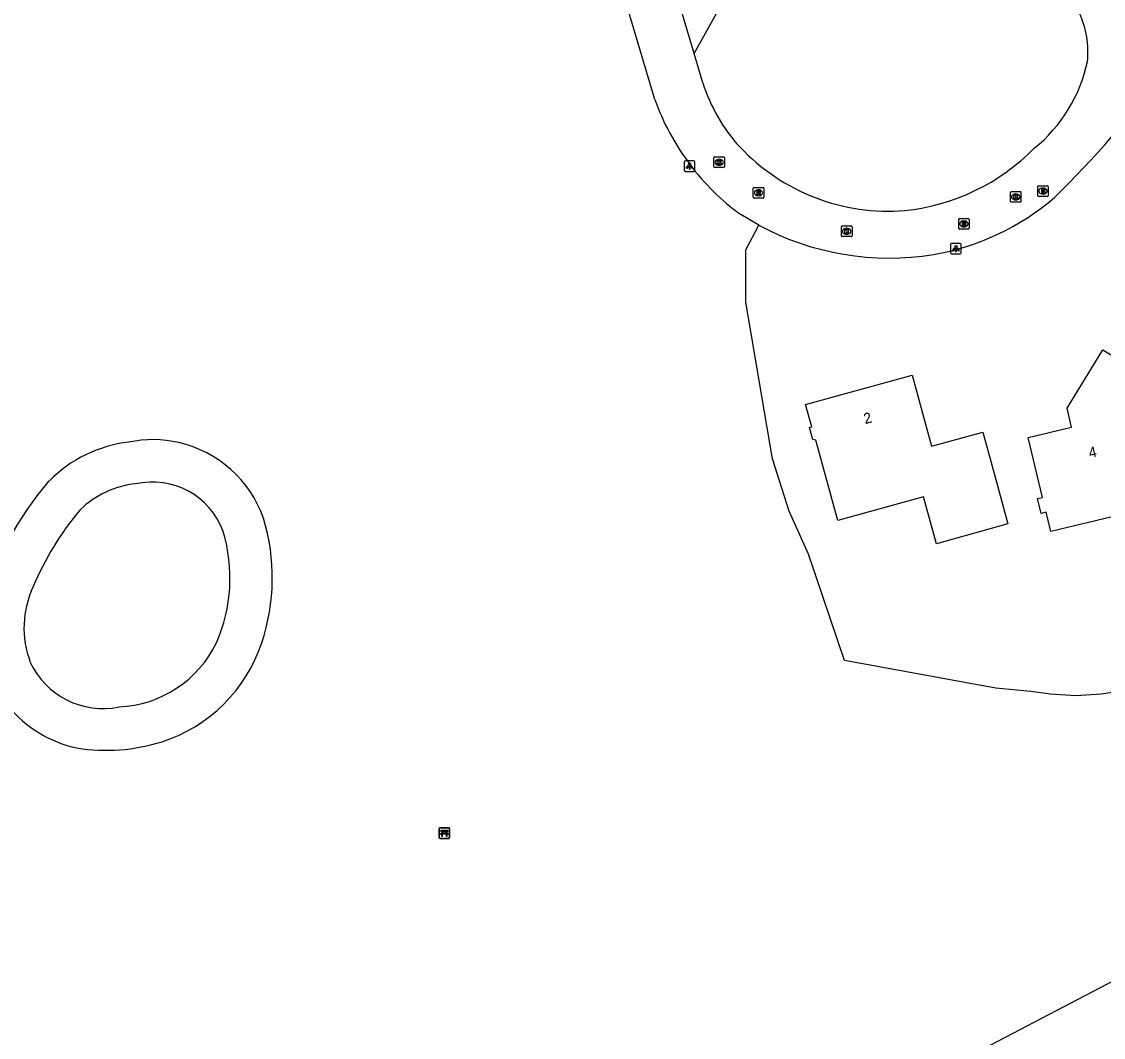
# Model space of a CAD drawing. Extents: x 162157 to 163165, y 378998 to 380775.
# Drawn here: x 162596.4 to 162698.9, y 380061.7 to 380157.8 of the extents above; entities that cross this region are included whole.
import ezdxf

# ---------------------------------------------------------------- set-up
doc = ezdxf.new("R2010")
doc.units = 0
for name, color, linetype in [('IMGEO_Bank', 7, 'Continuous'), ('IMGEO_Brandkraan', 7, 'Continuous'), ('IMGEO_Kolk', 7, 'Continuous'), ('IMGEO_Lichtpunt', 7, 'Continuous'), ('IMGEO_Meer_plas_ven_vijver', 7, 'Continuous'), ('IMGEO_Naaldbos', 7, 'Continuous'), ('IMGEO_Pand', 7, 'Continuous'), ('IMGEO_Pand_nummerreeks', 7, 'Continuous'), ('IMGEO_Rijbaan_lokaal_open', 7, 'Continuous'), ('IMGEO_Rioolput', 7, 'Continuous')]:
    doc.layers.add(name, color=color, linetype=linetype)

msp = doc.modelspace()

# ---------------------------------------------------------------- linework, layer by layer
at = {"layer": 'IMGEO_Bank'}
for p, q in [((162635.96, 380080.55), (162635.96, 380081.39)), ((162635.96, 380081.39), (162635.96, 380080.55)), ((162636.03, 380081.48), (162636.87, 380081.48)), ((162636.87, 380081.48), (162636.03, 380081.48)), ((162636.65, 380080.88), (162636.26, 380080.88)), ((162636.27, 380080.99), (162636.27, 380081.09)), ((162636.31, 380081.09), (162636.31, 380080.99)), ((162636.6, 380081.1), (162636.32, 380081.1)), ((162636.32, 380080.98), (162636.6, 380080.98)), ((162636.6, 380080.99), (162636.6, 380081.09)), ((162636.65, 380081.09), (162636.65, 380080.99)), ((162636.96, 380081.4), (162636.96, 380080.56)), ((162636.96, 380080.56), (162636.96, 380081.4)), ((162636.88, 380080.48), (162636.04, 380080.48)), ((162636.04, 380080.48), (162636.88, 380080.48))]:
    msp.add_line(p, q, dxfattribs=at)
for points in [[(162636.2, 380080.88), (162636.06, 380080.88), (162636.17, 380080.98), (162636.26, 380080.98)], [(162636.26, 380081.1), (162636.17, 380081.1), (162636.17, 380081.26), (162636.74, 380081.26), (162636.74, 380081.1), (162636.65, 380081.1)], [(162636.25, 380080.87), (162636.25, 380080.66), (162636.21, 380080.66), (162636.21, 380080.87)], [(162636.65, 380080.98), (162636.74, 380080.98), (162636.85, 380080.88), (162636.71, 380080.88)], [(162636.7, 380080.87), (162636.7, 380080.66), (162636.66, 380080.66), (162636.66, 380080.87)]]:
    msp.add_lwpolyline(points, dxfattribs=at)
for centre, radius, start, end in [((162636.04, 380081.4), 0.0779, 92.4484, 184.2845), ((162636.04, 380081.4), 0.0779, 92.4484, 184.2845), ((162636.2, 380080.87), 0.00671, 2.8957, 87.1043), ((162636.26, 380080.87), 0.00671, 92.8957, 177.1043), ((162636.26, 380081.09), 0.00671, 2.8957, 87.1043), ((162636.26, 380080.99), 0.00671, 272.8957, 357.1043), ((162636.32, 380081.09), 0.00671, 92.8957, 177.1043), ((162636.32, 380080.99), 0.00671, 182.8957, 267.1043), ((162636.6, 380081.09), 0.00671, 2.8957, 87.1043), ((162636.6, 380080.99), 0.00671, 272.8957, 357.1043), ((162636.65, 380081.09), 0.00671, 92.8957, 177.1043), ((162636.65, 380080.99), 0.00671, 182.8957, 267.1043), ((162636.65, 380080.87), 0.00671, 2.8957, 87.1043), ((162636.71, 380080.87), 0.00671, 92.8957, 177.1043), ((162636.88, 380081.4), 0.0779, 2.4484, 94.2845), ((162636.88, 380081.4), 0.0779, 2.4484, 94.2845), ((162636.04, 380080.56), 0.0779, 182.4484, 274.2845), ((162636.04, 380080.56), 0.0779, 182.4484, 274.2845), ((162636.88, 380080.56), 0.0779, 272.4484, 4.2845), ((162636.88, 380080.56), 0.0779, 272.4484, 4.2845)]:
    msp.add_arc(centre, radius, start, end, dxfattribs=at)
at = {"layer": 'IMGEO_Brandkraan'}
for p, q in [((162692.64, 380141.31), (162692.64, 380142.17)), ((162692.72, 380142.24), (162693.57, 380142.24)), ((162693.64, 380142.17), (162693.64, 380141.31)), ((162693.57, 380141.24), (162692.72, 380141.24)), ((162693.13, 380142.02), (162693.15, 380142.02)), ((162693.15, 380141.46), (162693.13, 380141.46))]:
    msp.add_line(p, q, dxfattribs=at)
for points in [[(162692.64, 380141.31), (162692.64, 380142.17)], [(162692.72, 380142.24), (162693.57, 380142.24)], [(162693.64, 380142.17), (162693.64, 380141.31)], [(162693.57, 380141.24), (162692.72, 380141.24)], [(162692.99, 380141.94), (162692.99, 380141.54), (162693.2, 380141.54)], [(162693.22, 380141.94), (162692.99, 380141.94)], [(162693.17, 380141.86), (162693.11, 380141.86), (162693.11, 380141.78)], [(162693.11, 380141.78), (162693.17, 380141.78)], [(162693.18, 380141.71), (162693.11, 380141.71), (162693.11, 380141.62)], [(162693.11, 380141.62), (162693.18, 380141.62)]]:
    msp.add_lwpolyline(points, dxfattribs=at)
for centre, radius, start, end in [((162692.72, 380142.16), 0.0765, 91.552, 178.448), ((162692.72, 380142.16), 0.0765, 91.552, 178.448), ((162693.57, 380142.16), 0.0765, 1.552, 88.448), ((162693.57, 380142.16), 0.0765, 1.552, 88.448), ((162692.72, 380141.31), 0.0765, 181.552, 268.448), ((162692.72, 380141.31), 0.0765, 181.552, 268.448), ((162693.17, 380141.82), 0.0379, 267.8285, 90.9355), ((162693.18, 380141.67), 0.0404, 269.8759, 90.5077), ((162693.21, 380141.79), 0.251, 268.6676, 293.5347), ((162693.22, 380141.79), 0.145, 59.4692, 91.5367), ((162693.25, 380141.84), 0.0922, 285.5137, 58.1501), ((162693.25, 380141.65), 0.105, 301.3115, 78.989), ((162693.57, 380141.31), 0.0765, 271.552, 358.448), ((162693.57, 380141.31), 0.0765, 271.552, 358.448)]:
    msp.add_arc(centre, radius, start, end, dxfattribs=at)
for centre, major_axis, ratio, start_param, end_param in [((162693.13, 380141.74), (-0.387, 0.002), 0.722429, 4.712389, 7.853982), ((162693.15, 380141.74), (-0.39, 0.002), 0.717154, 1.570796, 4.712389)]:
    msp.add_ellipse(centre, major_axis=major_axis, ratio=ratio, start_param=start_param, end_param=end_param, dxfattribs=at)
at = {"layer": 'IMGEO_Kolk'}
for p, q in [((162661.98, 380144.05), (162661.98, 380144.9)), ((162662.05, 380144.97), (162662.91, 380144.97)), ((162662.47, 380144.75), (162662.49, 380144.75)), ((162662.49, 380144.19), (162662.47, 380144.19)), ((162662.98, 380144.9), (162662.98, 380144.05)), ((162662.91, 380143.97), (162662.05, 380143.97)), ((162690.06, 380140.77), (162690.06, 380141.62)), ((162690.14, 380141.69), (162690.99, 380141.69)), ((162690.55, 380141.47), (162690.58, 380141.47)), ((162691.06, 380141.62), (162691.06, 380140.77)), ((162690.99, 380140.69), (162690.14, 380140.69)), ((162690.57, 380140.91), (162690.55, 380140.91)), ((162674.06, 380137.51), (162674.06, 380138.36)), ((162674.13, 380138.44), (162674.98, 380138.44)), ((162674.54, 380138.22), (162674.57, 380138.22)), ((162675.06, 380138.36), (162675.06, 380137.51)), ((162674.98, 380137.44), (162674.13, 380137.44)), ((162674.57, 380137.66), (162674.54, 380137.66))]:
    msp.add_line(p, q, dxfattribs=at)
for points in [[(162661.98, 380144.05), (162661.98, 380144.9)], [(162662.05, 380144.97), (162662.91, 380144.97)], [(162662.3, 380144.67), (162662.42, 380144.67), (162662.42, 380144.52), (162662.55, 380144.67), (162662.72, 380144.67), (162662.57, 380144.52), (162662.72, 380144.27), (162662.57, 380144.27), (162662.49, 380144.44), (162662.42, 380144.37), (162662.42, 380144.27), (162662.3, 380144.27), (162662.3, 380144.67)], [(162662.98, 380144.9), (162662.98, 380144.05)], [(162662.91, 380143.97), (162662.05, 380143.97)], [(162690.06, 380140.77), (162690.06, 380141.62)], [(162690.14, 380141.69), (162690.99, 380141.69)], [(162690.38, 380141.39), (162690.51, 380141.39), (162690.51, 380141.24), (162690.64, 380141.39), (162690.8, 380141.39), (162690.66, 380141.24), (162690.81, 380140.99), (162690.66, 380140.99), (162690.57, 380141.16), (162690.51, 380141.09), (162690.51, 380140.99), (162690.38, 380140.99), (162690.38, 380141.39)], [(162691.06, 380141.62), (162691.06, 380140.77)], [(162690.99, 380140.69), (162690.14, 380140.69)], [(162674.06, 380137.51), (162674.06, 380138.36)], [(162674.13, 380138.44), (162674.98, 380138.44)], [(162674.38, 380138.14), (162674.5, 380138.14), (162674.5, 380137.98), (162674.63, 380138.14), (162674.79, 380138.14), (162674.65, 380137.99), (162674.8, 380137.74), (162674.65, 380137.74), (162674.56, 380137.9), (162674.5, 380137.83), (162674.5, 380137.74), (162674.38, 380137.74), (162674.38, 380138.14)], [(162675.06, 380138.36), (162675.06, 380137.51)], [(162674.98, 380137.44), (162674.13, 380137.44)]]:
    msp.add_lwpolyline(points, dxfattribs=at)
for centre, start, end in [((162662.06, 380144.9), 91.552, 178.448), ((162662.06, 380144.9), 91.552, 178.448), ((162662.9, 380144.9), 1.552, 88.448), ((162662.9, 380144.9), 1.552, 88.448), ((162662.06, 380144.05), 181.552, 268.448), ((162662.06, 380144.05), 181.552, 268.448), ((162662.9, 380144.05), 271.552, 358.448), ((162662.9, 380144.05), 271.552, 358.448), ((162690.14, 380141.62), 91.552, 178.448), ((162690.14, 380141.62), 91.552, 178.448), ((162690.99, 380141.62), 1.552, 88.448), ((162690.99, 380141.62), 1.552, 88.448), ((162690.14, 380140.77), 181.552, 268.448), ((162690.14, 380140.77), 181.552, 268.448), ((162690.99, 380140.77), 271.552, 358.448), ((162690.99, 380140.77), 271.552, 358.448), ((162674.13, 380138.36), 91.552, 178.448), ((162674.13, 380138.36), 91.552, 178.448), ((162674.98, 380138.36), 1.552, 88.448), ((162674.98, 380138.36), 1.552, 88.448), ((162674.13, 380137.51), 181.552, 268.448), ((162674.13, 380137.51), 181.552, 268.448), ((162674.98, 380137.51), 271.552, 358.448), ((162674.98, 380137.51), 271.552, 358.448)]:
    msp.add_arc(centre, 0.0765, start, end, dxfattribs=at)
for centre, major_axis, ratio, start_param, end_param in [((162662.47, 380144.47), (-0.387, 0.002), 0.722429, 4.712389, 7.853982), ((162662.49, 380144.47), (-0.39, 0.002), 0.717154, 1.570796, 4.712389), ((162690.55, 380141.19), (-0.387, 0.002), 0.722429, 4.712389, 7.853982), ((162690.57, 380141.19), (-0.39, 0.002), 0.717154, 1.570796, 4.712389), ((162674.54, 380137.94), (-0.387, 0.002), 0.722429, 4.712389, 7.853982), ((162674.57, 380137.94), (-0.39, 0.002), 0.717154, 1.570796, 4.712389)]:
    msp.add_ellipse(centre, major_axis=major_axis, ratio=ratio, start_param=start_param, end_param=end_param, dxfattribs=at)
at = {"layer": 'IMGEO_Lichtpunt'}
for p, q in [((162659.18, 380144.51), (162659.18, 380143.7)), ((162659.18, 380144.51), (162659.18, 380143.7)), ((162660.09, 380144.6), (162659.28, 380144.6)), ((162660.09, 380144.6), (162659.28, 380144.6)), ((162660.18, 380143.7), (162660.18, 380144.51)), ((162660.18, 380143.7), (162660.18, 380144.51)), ((162659.28, 380143.61), (162660.09, 380143.61)), ((162659.28, 380143.61), (162660.09, 380143.61)), ((162684.4, 380136.69), (162684.4, 380135.89)), ((162684.4, 380136.69), (162684.4, 380135.89)), ((162685.3, 380136.79), (162684.49, 380136.79)), ((162685.3, 380136.79), (162684.49, 380136.79)), ((162685.39, 380135.89), (162685.39, 380136.69)), ((162685.39, 380135.89), (162685.39, 380136.69)), ((162684.49, 380135.79), (162685.3, 380135.79)), ((162684.49, 380135.79), (162685.3, 380135.79))]:
    msp.add_line(p, q, dxfattribs=at)
for points in [[(162659.56, 380144.17), (162659.6, 380144.14), (162659.41, 380143.88), (162659.37, 380143.91), (162659.56, 380144.17)], [(162659.66, 380144.12), (162659.71, 380144.12), (162659.71, 380143.8), (162659.66, 380143.8), (162659.66, 380144.12)], [(162659.77, 380144.14), (162659.81, 380144.17), (162659.99, 380143.91), (162659.96, 380143.88), (162659.77, 380144.14)], [(162684.77, 380136.36), (162684.81, 380136.33), (162684.62, 380136.07), (162684.58, 380136.09), (162684.77, 380136.36)], [(162684.87, 380136.31), (162684.92, 380136.31), (162684.92, 380135.99), (162684.87, 380135.99), (162684.87, 380136.31)], [(162684.98, 380136.33), (162685.02, 380136.36), (162685.21, 380136.09), (162685.17, 380136.07), (162684.98, 380136.33)]]:
    msp.add_lwpolyline(points, dxfattribs=at)
for centre in [(162659.68, 380144.31), (162684.9, 380136.49)]:
    msp.add_circle(centre, 0.0994, dxfattribs=at)
for centre, start, end in [((162659.28, 380144.51), 90, 180), ((162659.28, 380144.51), 90, 180), ((162660.09, 380144.51), 0, 90), ((162660.09, 380144.51), 0, 90), ((162659.28, 380143.7), 180, 270), ((162659.28, 380143.7), 180, 270), ((162660.09, 380143.7), 270, 0), ((162660.09, 380143.7), 270, 360), ((162684.49, 380136.69), 90, 180), ((162684.49, 380136.69), 90, 180), ((162684.49, 380135.89), 180, 270), ((162684.49, 380135.89), 180, 270), ((162685.3, 380136.69), 0, 90), ((162685.3, 380136.69), 0, 90), ((162685.3, 380135.89), 270, 0), ((162685.3, 380135.89), 270, 360)]:
    msp.add_arc(centre, 0.0946, start, end, dxfattribs=at)
at = {"layer": 'IMGEO_Meer_plas_ven_vijver'}
for centre, radius, start, end in [((162608.09, 380105.35), 8.73, 95.7071, 134.4879), ((162608.82, 380107.08), 7.13, 20.0147, 102.9648), ((162623.53, 380093.38), 28.21, 139.8402, 157.1735), ((162600.81, 380105.13), 15.35, 336.4564, 16.6153), ((162605.75, 380100.41), 9.1, 154.4911, 200.9768), ((162605.17, 380103.72), 10.8, 272.5827, 334.1187), ((162604.15, 380100.4), 7.63, 205.2539, 281.4036)]:
    msp.add_arc(centre, radius, start, end, dxfattribs=at)
at = {"layer": 'IMGEO_Naaldbos'}
for points in [[(162660.11, 380154.75), (162672.95, 380177.83), (162681.9, 380184), (162683.75, 380185.24)], [(162731.65, 380103.3), (162714.75, 380099.44), (162709.98, 380097.79), (162706.23, 380096.19), (162704.59, 380095.45), (162702.89, 380094.89), (162700.99, 380094.49), (162698.64, 380094.12), (162696.25, 380093.99), (162693.87, 380094.12), (162691.98, 380094.4), (162688.68, 380094.71), (162674.35, 380097.31), (162670.94, 380107.39), (162669.1, 380111.45), (162667.52, 380116.4), (162665.02, 380131.24), (162664.99, 380136.17), (162666.23, 380138.52)], [(162593.16, 380104.07), (162593.5, 380105.07), (162593.87, 380105.94), (162594.51, 380107.36), (162595.25, 380108.8), (162596.07, 380110.21), (162596.95, 380111.57), (162597.9, 380112.89), (162599.05, 380114.33)], [(162729.41, 380100.06), (162720.42, 380098.09), (162713.95, 380095.98), (162707.67, 380093.67), (162709.55, 380072.09), (162684.74, 380059.13), (162663.78, 380052.37)]]:
    msp.add_lwpolyline(points, dxfattribs=at)
for centre, radius, start, end in [((162608.06, 380105.36), 12.71, 96.6944, 135.1126), ((162608.84, 380107.27), 10.95, 76.931, 101.9328), ((162608.82, 380107.07), 11.15, 19.4918, 77.0249), ((162600.77, 380105.14), 19.4, 341.487, 16.9112), ((162605.24, 380103.6), 14.67, 287.8427, 341.6753), ((162604.15, 380100.41), 11.64, 219.5455, 257.5947), ((162604.45, 380106.39), 17.57, 260.8404, 287.5081)]:
    msp.add_arc(centre, radius, start, end, dxfattribs=at)
at = {"layer": 'IMGEO_Pand'}
for points in [[(162704.58, 380112.09), (162693.9, 380109.52), (162693.45, 380111.35), (162692.96, 380111.23), (162692.62, 380112.65), (162693.1, 380112.76), (162691.74, 380118.42), (162695.85, 380119.41), (162695.42, 380121.2), (162697.16, 380124.05), (162698.71, 380126.57), (162698.8, 380126.72), (162700.42, 380125.73), (162701.61, 380120.8), (162702.43, 380121), (162703.6, 380116.14), (162704.58, 380112.09)], [(162688.77, 380114.11), (162689.83, 380110.24), (162683.06, 380108.37), (162681.83, 380112.81), (162673.73, 380110.57), (162671.64, 380118.16), (162671.36, 380118.23), (162671.04, 380119.37), (162671.25, 380119.43), (162670.67, 380121.53), (162680.74, 380124.31), (162682.59, 380117.6), (162687.44, 380118.94), (162688.77, 380114.11)]]:
    msp.add_lwpolyline(points, dxfattribs=at)
at = {"layer": 'IMGEO_Rijbaan_lokaal_open'}
for points in [[(162660.11, 380154.75), (162653.57, 380176.75)], [(162656.39, 380150.41), (162649.98, 380171.96), (162649.71, 380172.51), (162649.43, 380173.06), (162649.29, 380173.33), (162649.09, 380173.72)], [(162660.93, 380151.99), (162660.11, 380154.75)], [(162666.23, 380138.52), (162664.52, 380139.52)]]:
    msp.add_lwpolyline(points, dxfattribs=at)
for centre, radius, start, end in [((162688.65, 380154.93), 8.75, 353.8956, 24.664), ((162683.2, 380157.04), 14.48, 309.0155, 347.863), ((162614.62, 380221.79), 113.33, 314.6334, 322.5903), ((162676.53, 380156.97), 16.38, 197.7026, 222.3742), ((162678.04, 380158.14), 22.99, 199.6453, 217.0931), ((162678.49, 380159.09), 19.25, 223.1001, 274.7149), ((162677.9, 380160.07), 20.29, 276.155, 315.2697), ((162678.06, 380158.1), 22.99, 216.9928, 233.9172), ((162678.78, 380159.06), 23.66, 279.726, 310.8004), ((162678.61, 380161.54), 26.14, 241.7233, 279.1837)]:
    msp.add_arc(centre, radius, start, end, dxfattribs=at)
at = {"layer": 'IMGEO_Rioolput'}
for p, q in [((162665.79, 380142.09), (162666.64, 380142.09)), ((162665.71, 380141.16), (162665.71, 380142.01)), ((162666.64, 380141.08), (162665.79, 380141.08)), ((162666.2, 380141.86), (162666.22, 380141.86)), ((162666.22, 380141.31), (162666.2, 380141.31)), ((162666.71, 380142.01), (162666.71, 380141.16)), ((162685.16, 380138.21), (162685.16, 380139.07)), ((162685.23, 380139.14), (162686.09, 380139.14)), ((162686.16, 380139.07), (162686.16, 380138.21)), ((162686.09, 380138.14), (162685.23, 380138.14)), ((162685.65, 380138.92), (162685.67, 380138.92)), ((162685.67, 380138.36), (162685.65, 380138.36))]:
    msp.add_line(p, q, dxfattribs=at)
for points in [[(162665.79, 380142.09), (162666.64, 380142.09)], [(162665.71, 380141.16), (162665.71, 380142.01)], [(162666.64, 380141.08), (162665.79, 380141.08)], [(162666.3, 380141.78), (162666.05, 380141.78), (162666.05, 380141.38)], [(162666.05, 380141.38), (162666.17, 380141.38), (162666.17, 380141.55), (162666.18, 380141.55)], [(162666.23, 380141.7), (162666.17, 380141.7), (162666.17, 380141.62)], [(162666.17, 380141.62), (162666.22, 380141.62)], [(162666.23, 380141.52), (162666.3, 380141.38), (162666.44, 380141.38), (162666.38, 380141.51)], [(162666.71, 380142.01), (162666.71, 380141.16)], [(162685.16, 380138.21), (162685.16, 380139.07)], [(162685.23, 380139.14), (162686.09, 380139.14)], [(162686.16, 380139.07), (162686.16, 380138.21)], [(162686.09, 380138.14), (162685.23, 380138.14)], [(162685.75, 380138.84), (162685.5, 380138.84), (162685.5, 380138.44)], [(162685.5, 380138.44), (162685.62, 380138.44), (162685.62, 380138.6), (162685.63, 380138.6)], [(162685.68, 380138.76), (162685.62, 380138.76), (162685.62, 380138.68)], [(162685.62, 380138.68), (162685.67, 380138.68)], [(162685.68, 380138.57), (162685.75, 380138.44), (162685.89, 380138.44), (162685.82, 380138.57)]]:
    msp.add_lwpolyline(points, dxfattribs=at)
for centre, radius, start, end in [((162665.79, 380142.01), 0.0765, 91.552, 178.448), ((162665.79, 380142.01), 0.0765, 91.552, 178.448), ((162666.64, 380142.01), 0.0765, 1.552, 88.448), ((162666.64, 380142.01), 0.0765, 1.552, 88.448), ((162665.79, 380141.16), 0.0765, 181.552, 268.448), ((162665.79, 380141.16), 0.0765, 181.552, 268.448), ((162666.18, 380141.49), 0.0533, 26.0293, 88.6989), ((162666.21, 380141.81), 0.19, 274.7715, 282.9687), ((162666.23, 380141.61), 0.0964, 77.0061, 93.1865), ((162666.25, 380141.66), 0.0378, 276.6634, 79.6772), ((162666.3, 380141.67), 0.109, 350.3612, 89.416), ((162666.3, 380141.67), 0.112, 277.5842, 350.9817), ((162666.28, 380141.46), 0.108, 29.5134, 73.7905), ((162666.64, 380141.16), 0.0765, 271.552, 358.448), ((162666.64, 380141.16), 0.0765, 271.552, 358.448), ((162685.24, 380139.06), 0.0765, 91.552, 178.448), ((162685.24, 380139.06), 0.0765, 91.552, 178.448), ((162686.08, 380139.06), 0.0765, 1.552, 88.448), ((162686.08, 380139.06), 0.0765, 1.552, 88.448), ((162685.24, 380138.22), 0.0765, 181.552, 268.448), ((162685.24, 380138.22), 0.0765, 181.552, 268.448), ((162685.63, 380138.55), 0.0533, 26.0293, 88.6989), ((162685.66, 380138.87), 0.19, 274.7715, 282.9687), ((162685.68, 380138.66), 0.0964, 77.0061, 93.1865), ((162685.7, 380138.72), 0.0378, 276.6634, 79.6772), ((162685.75, 380138.73), 0.109, 350.3612, 89.416), ((162685.75, 380138.73), 0.112, 277.5842, 350.9817), ((162685.73, 380138.51), 0.108, 29.5134, 73.7905), ((162686.08, 380138.22), 0.0765, 271.552, 358.448), ((162686.08, 380138.22), 0.0765, 271.552, 358.448)]:
    msp.add_arc(centre, radius, start, end, dxfattribs=at)
for centre, major_axis, ratio, start_param, end_param in [((162666.2, 380141.58), (-0.387, 0.002), 0.722429, 4.712389, 7.853982), ((162666.22, 380141.58), (-0.39, 0.002), 0.717154, 1.570796, 4.712389), ((162685.65, 380138.64), (-0.387, 0.002), 0.722429, 4.712389, 7.853982), ((162685.67, 380138.64), (-0.39, 0.002), 0.717154, 1.570796, 4.712389)]:
    msp.add_ellipse(centre, major_axis=major_axis, ratio=ratio, start_param=start_param, end_param=end_param, dxfattribs=at)

# ---------------------------------------------------------------- texts
at = {"layer": 'IMGEO_Pand_nummerreeks'}
for s, rotation, p in [('2', 15.4172, (162676.31, 380119.68)), ('4', 13.5778, (162697.59, 380116.46))]:
    msp.add_text(s, height=1, rotation=rotation, dxfattribs=at).set_placement(p)

doc.saveas('drawing.dxf')
